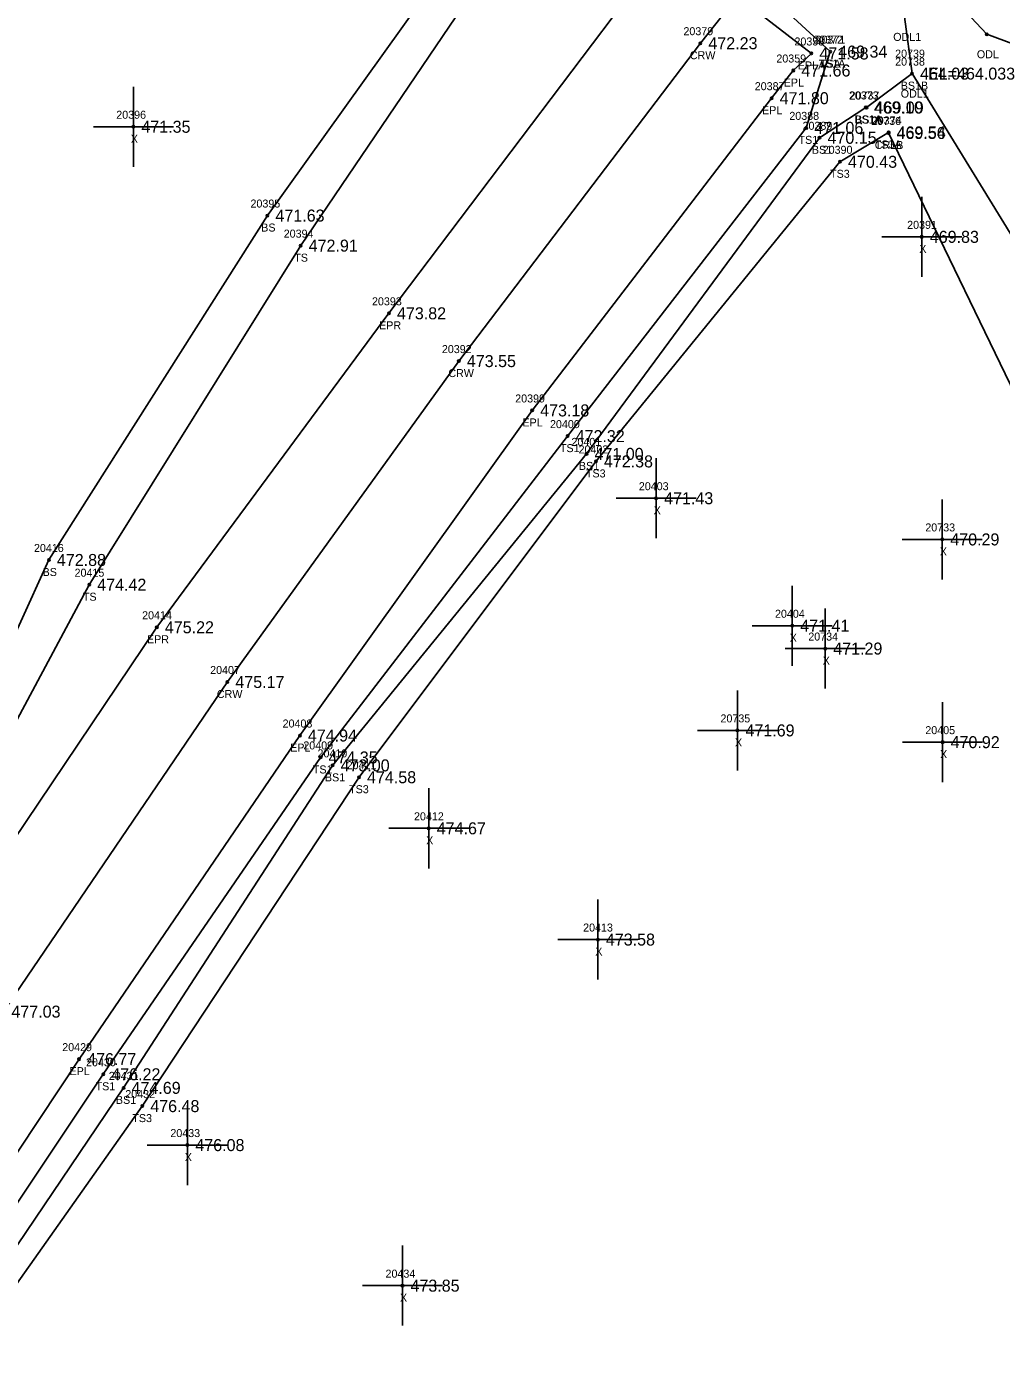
# Model space of a CAD drawing. Extents: x 1741010 to 1742139, y 749382 to 750625.
# Drawn here: x 1741494.6 to 1741616.4, y 749875.8 to 750041.3 of the extents above; entities that cross this region are included whole.
import ezdxf

# ---------------------------------------------------------------- set-up
doc = ezdxf.new("R2010")
doc.units = 0
for name, color, linetype in [('RD_DTM_BkLn1', 7, 'Continuous'), ('RD_DTM_BkLn2', 7, 'Continuous'), ('RD_DTM_BkLn_txCode', 7, 'Continuous'), ('RD_EX_H2O', 7, 'Continuous'), ('RD_EX_H2O_txCode', 7, 'Continuous'), ('RD_EX_Misc', 7, 'Continuous'), ('RD_EX_Misc_txCode', 7, 'Continuous'), ('RD_EX_Road', 7, 'Continuous'), ('RD_EX_Road_txCode', 7, 'Continuous'), ('RD_EX_TX_H2O_ELEV', 7, 'Continuous'), ('RD_EX_TX_Misc_ELEV', 7, 'Continuous'), ('RD_EX_TX_Road_ELEV', 7, 'Continuous'), ('RD_HC_Survey_ELEV', 7, 'Continuous'), ('RD_HC_Survey_txCode', 7, 'Continuous'), ('RD_SMD_Locator', 7, 'Continuous')]:
    doc.layers.add(name, color=color, linetype=linetype)

msp = doc.modelspace()

# ---------------------------------------------------------------- linework, layer by layer
at = {"layer": 'RD_DTM_BkLn1'}
msp.add_lwpolyline([(1741583.42, 750045.09), (1741578.78, 750039.19), (1741548.6, 749999.46), (1741519.68, 749959.35), (1741491.7, 749918.15), (1741464.01, 749876.67), (1741436.51, 749835.23), (1741409.05, 749793.46), (1741381.95, 749752.07), (1741327.4, 749668.12), (1741273.18, 749584.75), (1741218.51, 749501.3), (1741163.8, 749416.96)], dxfattribs=at)
at = {"layer": 'RD_DTM_BkLn2'}
msp.add_line((1741599.54, 750031.15), (1741605.22, 750035.39), dxfattribs=at)
for points in [[(1741595, 750038.14), (1741574.61, 750056.92), (1741567.17, 750063.05), (1741557.5, 750056.24), (1741528.84, 750013.89), (1741502.42, 749971.51), (1741486.02, 749940.89), (1741477.71, 749927.84), (1741450.78, 749885.21), (1741423.85, 749843.58), (1741396.77, 749800.81), (1741369.66, 749759.51), (1741314.64, 749675.74), (1741265.52, 749598.52), (1741262.68, 749595.73), (1741260.89, 749596.52)], [(1741553.69, 750058.21), (1741524.69, 750017.65), (1741497.38, 749974.6), (1741482.49, 749941.95), (1741475.22, 749929.78), (1741449.41, 749886.55), (1741422.56, 749844.68), (1741395.22, 749801.69), (1741368.2, 749760.22), (1741313.51, 749676.19), (1741261.6, 749597.61)], [(1741592.65, 750037.91), (1741583.42, 750045.09), (1741574.14, 750053.03)], [(1741595, 750038.14), (1741592, 750028.61), (1741562.19, 749990.08), (1741531.32, 749949.92), (1741504.18, 749910.32), (1741476.42, 749868.74), (1741449.21, 749826.98), (1741421.85, 749784.9), (1741395.46, 749743.34), (1741340.74, 749659.13), (1741287.12, 749574.46), (1741231.7, 749491.89), (1741176.84, 749408.86)], [(1741599.45, 750031.16), (1741593.66, 750027.37), (1741564.55, 749987.86), (1741532.82, 749948.93), (1741506.71, 749908.62), (1741479.05, 749867.73), (1741451.41, 749825.96), (1741424.08, 749783.57), (1741397.6, 749742.18), (1741343.11, 749657.77), (1741289.87, 749573.19), (1741234.86, 749489.33), (1741179.61, 749406.64)], [(1741602.3, 750028.04), (1741596.22, 750024.37), (1741565.72, 749986.92), (1741536.13, 749947.45), (1741509.05, 749906.34), (1741480.78, 749866.4), (1741453.63, 749824.8), (1741427.39, 749781.55), (1741401.53, 749739.33), (1741346.85, 749655.57), (1741291.93, 749571.65), (1741238.4, 749487.04), (1741181.74, 749404.39)]]:
    msp.add_lwpolyline(points, dxfattribs=at)
at = {"layer": 'RD_EX_H2O'}
for points in [[(1741621.8, 750037.62), (1741614.56, 750040.31), (1741609.32, 750045.96)], [(1741979.95, 749694.15), (1741975.81, 749711.2), (1741958.44, 749721.88), (1741894.61, 749726.87), (1741877.76, 749724.44), (1741850.91, 749736.65), (1741828.26, 749780.7), (1741797.14, 749817.35), (1741808.22, 749831.81), (1741810.09, 749840.16), (1741785.92, 749848.46), (1741738.7, 749880.42), (1741729.53, 749896.38), (1741713.46, 749926.44), (1741709.24, 749941.41), (1741681.29, 749963.78), (1741670.93, 749974.67), (1741649.76, 749966.83), (1741639.61, 749974.72), (1741630.05, 749994.96), (1741605.22, 750035.39), (1741604.28, 750042.48)], [(1741676.89, 749954.42), (1741667.36, 749953.74), (1741640.04, 749960.58), (1741631.9, 749972.55), (1741621.31, 749988.66), (1741602.28, 750027.97)]]:
    msp.add_lwpolyline(points, dxfattribs=at)
at = {"layer": 'RD_EX_Misc'}
for p, q in [((1741507.94, 750023.75), (1741507.94, 750033.75)), ((1741502.94, 750028.75), (1741512.94, 750028.75)), ((1741606.44, 750009.99), (1741606.44, 750019.99)), ((1741601.44, 750014.99), (1741611.44, 750014.99)), ((1741573.25, 749977.32), (1741573.25, 749987.32)), ((1741568.25, 749982.32), (1741578.25, 749982.32)), ((1741609, 749972.17), (1741609, 749982.17)), ((1741604, 749977.17), (1741614, 749977.17)), ((1741590.25, 749961.38), (1741590.25, 749971.38)), ((1741594.38, 749958.53), (1741594.38, 749968.53)), ((1741585.25, 749966.38), (1741595.25, 749966.38)), ((1741589.38, 749963.53), (1741599.38, 749963.53)), ((1741583.41, 749948.3), (1741583.41, 749958.3)), ((1741609.04, 749946.83), (1741609.04, 749956.83)), ((1741578.41, 749953.3), (1741588.41, 749953.3)), ((1741604.04, 749951.83), (1741614.04, 749951.83)), ((1741544.84, 749936.06), (1741544.84, 749946.06)), ((1741539.84, 749941.06), (1741549.84, 749941.06)), ((1741565.97, 749922.16), (1741565.97, 749932.16)), ((1741560.97, 749927.16), (1741570.97, 749927.16)), ((1741514.68, 749896.47), (1741514.68, 749906.47)), ((1741509.68, 749901.47), (1741519.68, 749901.47)), ((1741541.56, 749878.9), (1741541.56, 749888.9)), ((1741536.56, 749883.9), (1741546.56, 749883.9))]:
    msp.add_line(p, q, dxfattribs=at)
at = {"layer": 'RD_EX_Road'}
for points in [[(1741574.14, 750053.03), (1741573.09, 750050.35), (1741570.35, 750045.84), (1741539.87, 750005.43), (1741510.87, 749966.19), (1741482.97, 749924.75), (1741454.76, 749883.01), (1741427.14, 749841.37), (1741399.6, 749799.14), (1741372.83, 749758.13), (1741317.93, 749673.6), (1741267.39, 749595.97), (1741263.6, 749591.05), (1741254, 749576.22), (1741209.28, 749507.22), (1741154.74, 749422.71)], [(1741592.65, 750037.91), (1741590.39, 750035.78), (1741587.68, 750032.32), (1741557.76, 749993.29), (1741528.74, 749952.66), (1741501.16, 749912.21), (1741473.5, 749870.53), (1741446.05, 749829.26), (1741418.1, 749787.13), (1741391.18, 749745.79), (1741336.54, 749661.65), (1741282.05, 749578.36), (1741227.71, 749494.6), (1741173.28, 749411)]]:
    msp.add_lwpolyline(points, dxfattribs=at)
at = {"layer": 'RD_SMD_Locator'}
for centre in [(1741614.56, 750040.31), (1741578.78, 750039.19), (1741592.65, 750037.91), (1741595, 750038.14), (1741595, 750038.14), (1741590.39, 750035.78), (1741605.22, 750035.39), (1741605.22, 750035.39), (1741587.68, 750032.32), (1741599.45, 750031.16), (1741599.54, 750031.15), (1741507.94, 750028.75), (1741592, 750028.61), (1741593.66, 750027.37), (1741602.28, 750027.97), (1741602.3, 750028.04), (1741596.22, 750024.37), (1741524.69, 750017.65), (1741528.84, 750013.89), (1741606.44, 750014.99), (1741539.87, 750005.43), (1741548.6, 749999.46), (1741557.76, 749993.29), (1741562.19, 749990.08), (1741564.55, 749987.86), (1741565.72, 749986.92), (1741573.25, 749982.32), (1741609, 749977.17), (1741497.38, 749974.6), (1741502.42, 749971.51), (1741510.87, 749966.19), (1741590.25, 749966.38), (1741594.38, 749963.53), (1741519.68, 749959.35), (1741528.74, 749952.66), (1741583.41, 749953.3), (1741609.04, 749951.83), (1741531.32, 749949.92), (1741532.82, 749948.93), (1741536.13, 749947.45), (1741544.84, 749941.06), (1741565.97, 749927.16), (1741501.16, 749912.21), (1741504.18, 749910.32), (1741506.71, 749908.62), (1741509.05, 749906.34), (1741514.68, 749901.47), (1741541.56, 749883.9)]:
    msp.add_circle(centre, 0.15, dxfattribs=at)

# ---------------------------------------------------------------- texts
at = {"layer": 'RD_DTM_BkLn_txCode'}
for s, p in [('20372', (1741592.88, 750039.14)), ('20371', (1741593.16, 750039.14)), ('TS1A', (1741593.55, 750036.14)), ('TSA', (1741593.71, 750036.14)), ('20738', (1741603.11, 750036.39)), ('BS1B', (1741603.81, 750033.39)), ('20373', (1741597.33, 750032.16)), ('20737', (1741597.42, 750032.15)), ('20388', (1741589.89, 750029.61)), ('20389', (1741591.54, 750028.37)), ('BS1A', (1741598.02, 750029.16)), ('BS1A', (1741598.11, 750029.15)), ('20374', (1741600.19, 750029.04)), ('TS1', (1741591.04, 750026.61)), ('TS3A', (1741600.57, 750026.04)), ('BS1', (1741592.71, 750025.37)), ('20390', (1741594.06, 750025.37)), ('TS3', (1741594.98, 750022.37)), ('20395', (1741522.57, 750018.65)), ('BS', (1741523.91, 750015.65)), ('20394', (1741526.72, 750014.89)), ('TS', (1741528.04, 750011.89)), ('20400', (1741559.99, 749991.08)), ('TS1', (1741561.23, 749988.08)), ('20401', (1741562.67, 749988.86)), ('20402', (1741563.56, 749987.92)), ('BS1', (1741563.6, 749985.86)), ('TS3', (1741564.48, 749984.92)), ('20416', (1741495.52, 749975.6)), ('BS', (1741496.6, 749972.6)), ('20415', (1741500.59, 749972.51)), ('TS', (1741501.63, 749969.51)), ('20409', (1741529.17, 749950.92)), ('20410', (1741530.94, 749949.93)), ('20411', (1741534.58, 749948.45)), ('TS1', (1741530.36, 749947.92)), ('BS1', (1741531.87, 749946.93)), ('TS3', (1741534.89, 749945.45)), ('20430', (1741502.02, 749911.32)), ('20431', (1741504.87, 749909.62)), ('TS1', (1741503.22, 749908.32)), ('20432', (1741506.93, 749907.34)), ('BS1', (1741505.76, 749906.62)), ('TS3', (1741507.81, 749904.34))]:
    msp.add_text(s, height=1, dxfattribs=at).set_placement(p)
at = {"layer": 'RD_EX_H2O_txCode'}
for s, p in [('ODL1', (1741602.87, 750039.48)), ('20739', (1741603.11, 750037.39)), ('ODL', (1741613.32, 750037.31)), ('ODL1', (1741603.81, 750032.39)), ('20736', (1741600.13, 750028.97)), ('CRLB', (1741600.57, 750025.97))]:
    msp.add_text(s, height=1, dxfattribs=at).set_placement(p)
at = {"layer": 'RD_EX_Misc_txCode'}
for s, p in [('20396', (1741505.8, 750029.75)), ('X', (1741507.62, 750026.75)), ('20391', (1741604.61, 750015.99)), ('X', (1741606.13, 750012.99)), ('20403', (1741571.09, 749983.32)), ('X', (1741572.94, 749980.32)), ('20733', (1741606.88, 749978.17)), ('X', (1741608.69, 749975.17)), ('20404', (1741588.1, 749967.38)), ('X', (1741589.94, 749964.38)), ('20734', (1741592.26, 749964.53)), ('X', (1741594.06, 749961.53)), ('20735', (1741581.29, 749954.3)), ('20405', (1741606.88, 749952.83)), ('X', (1741583.1, 749951.3)), ('X', (1741608.72, 749949.83)), ('20412', (1741543, 749942.06)), ('X', (1741544.52, 749939.06)), ('20413', (1741564.13, 749928.16)), ('X', (1741565.65, 749925.16)), ('20433', (1741512.56, 749902.47)), ('X', (1741514.36, 749899.47)), ('20434', (1741539.44, 749884.9)), ('X', (1741541.25, 749881.9))]:
    msp.add_text(s, height=1, dxfattribs=at).set_placement(p)
at = {"layer": 'RD_EX_Road_txCode'}
for s, p in [('20358', (1741590.53, 750038.91)), ('20359', (1741588.27, 750036.78)), ('EPLA', (1741590.95, 750035.91)), ('20387', (1741585.57, 750033.32)), ('EPL', (1741589.19, 750033.78)), ('EPL', (1741586.48, 750030.32)), ('20393', (1741537.75, 750006.43)), ('EPR', (1741538.64, 750003.43)), ('20399', (1741555.64, 749994.29)), ('EPL', (1741556.55, 749991.29)), ('20414', (1741509.03, 749967.19)), ('EPR', (1741509.64, 749964.19)), ('20408', (1741526.58, 749953.66)), ('EPL', (1741527.53, 749950.66)), ('20429', (1741499.05, 749913.21)), ('EPL', (1741499.96, 749910.21))]:
    msp.add_text(s, height=1, dxfattribs=at).set_placement(p)
at = {"layer": 'RD_EX_TX_H2O_ELEV'}
for s, p in [('EL=464.033', (1741607.22, 750034.64)), ('469.56', (1741603.28, 750027.22))]:
    msp.add_text(s, height=1.5, dxfattribs=at).set_placement(p)
at = {"layer": 'RD_EX_TX_Misc_ELEV'}
for s, p in [('469.34', (1741596, 750037.39)), ('469.34', (1741596, 750037.39)), ('464.03', (1741606.22, 750034.64)), ('469.10', (1741600.45, 750030.41)), ('469.09', (1741600.54, 750030.4)), ('471.35', (1741508.94, 750028)), ('471.06', (1741593, 750027.86)), ('469.54', (1741603.3, 750027.29)), ('470.15', (1741594.66, 750026.62)), ('470.43', (1741597.22, 750023.62)), ('471.63', (1741525.69, 750016.9)), ('469.83', (1741607.44, 750014.24)), ('472.91', (1741529.84, 750013.14)), ('472.32', (1741563.19, 749989.33)), ('471.00', (1741565.55, 749987.11)), ('472.38', (1741566.72, 749986.17)), ('471.43', (1741574.25, 749981.57)), ('470.29', (1741610, 749976.42)), ('472.88', (1741498.38, 749973.85)), ('474.42', (1741503.42, 749970.76)), ('471.41', (1741591.25, 749965.63)), ('471.29', (1741595.38, 749962.78)), ('471.69', (1741584.41, 749952.55)), ('470.92', (1741610.04, 749951.08)), ('474.35', (1741532.32, 749949.17)), ('473.00', (1741533.82, 749948.18)), ('474.58', (1741537.13, 749946.7)), ('474.67', (1741545.84, 749940.31)), ('473.58', (1741566.97, 749926.41)), ('476.22', (1741505.18, 749909.57)), ('474.69', (1741507.71, 749907.87)), ('476.48', (1741510.05, 749905.59)), ('476.08', (1741515.68, 749900.72)), ('473.85', (1741542.56, 749883.15))]:
    msp.add_text(s, height=1.5, dxfattribs=at).set_placement(p)
at = {"layer": 'RD_EX_TX_Road_ELEV'}
for s, p in [('471.58', (1741593.65, 750037.16)), ('471.66', (1741591.39, 750035.03)), ('471.80', (1741588.68, 750031.57)), ('473.82', (1741540.87, 750004.68)), ('473.18', (1741558.76, 749992.54)), ('475.22', (1741511.87, 749965.44)), ('474.94', (1741529.74, 749951.91)), ('476.77', (1741502.16, 749911.46))]:
    msp.add_text(s, height=1.5, dxfattribs=at).set_placement(p)
at = {"layer": 'RD_HC_Survey_ELEV'}
for s, p in [('472.23', (1741579.78, 750038.44)), ('473.55', (1741549.6, 749998.71)), ('475.17', (1741520.68, 749958.6)), ('477.03', (1741492.7, 749917.4))]:
    msp.add_text(s, height=1.5, dxfattribs=at).set_placement(p)
at = {"layer": 'RD_HC_Survey_txCode'}
for s, p in [('20379', (1741576.66, 750040.19)), ('CRW', (1741577.46, 750037.19)), ('20392', (1741546.48, 750000.46)), ('CRW', (1741547.29, 749997.46)), ('20407', (1741517.53, 749960.35)), ('CRW', (1741518.37, 749957.35))]:
    msp.add_text(s, height=1, dxfattribs=at).set_placement(p)

doc.saveas('drawing.dxf')
